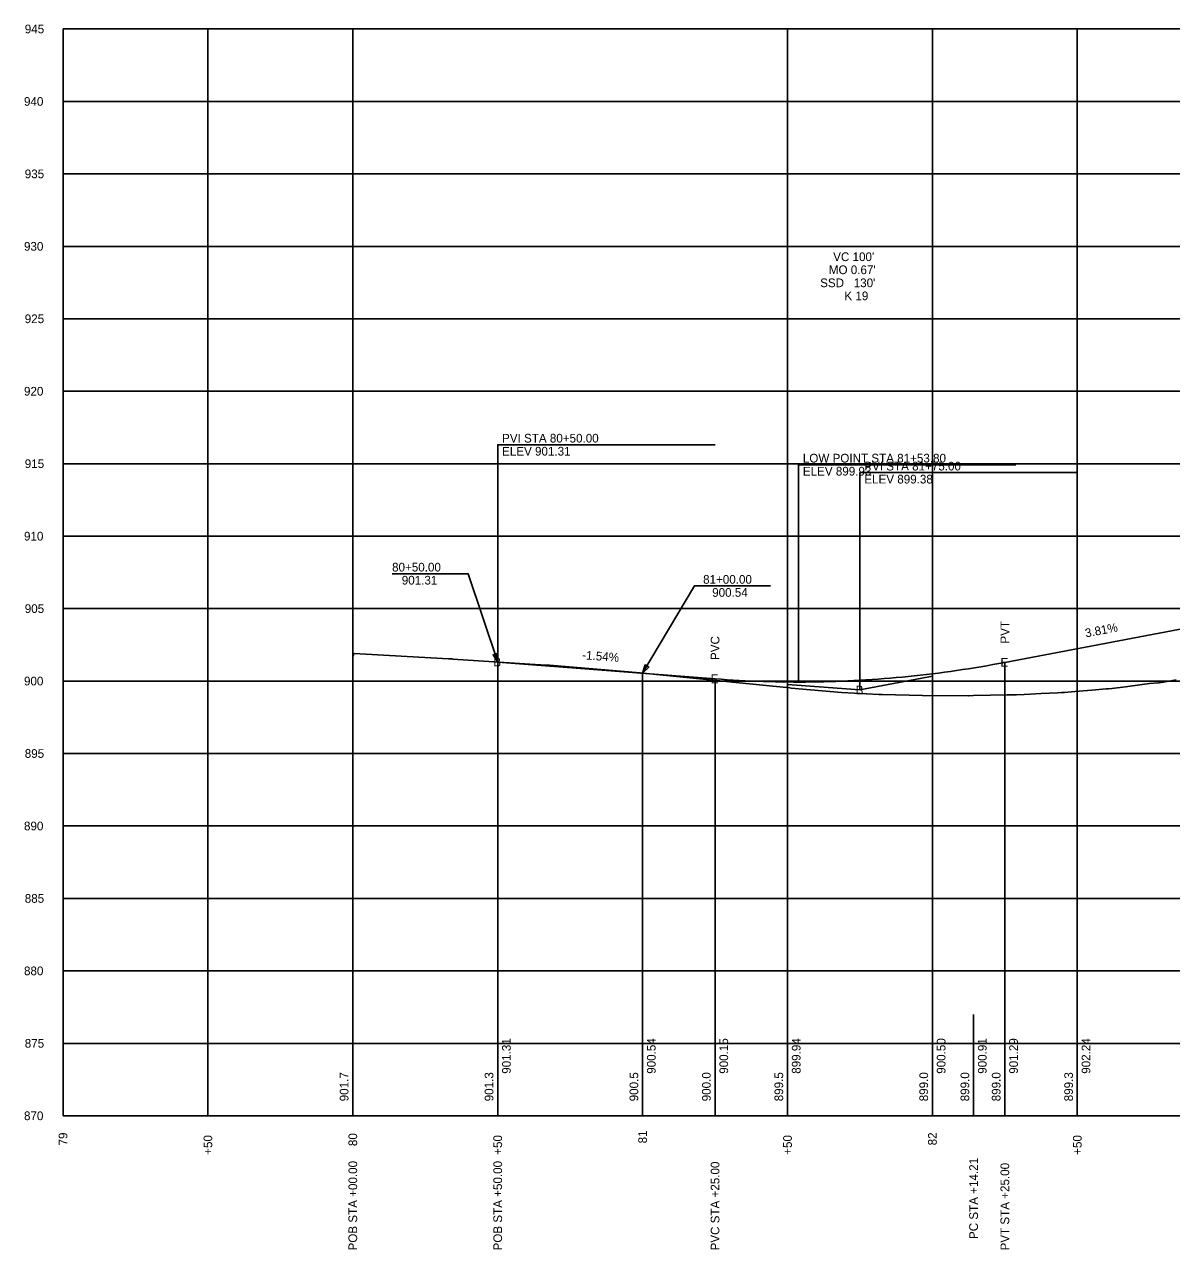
# Model space of a CAD drawing. Extents: x 76292 to 78417, y 50412 to 52585.
# Drawn here: x 76292.1 to 76687.8, y 51114.2 to 51536.9 of the extents above; entities that cross this region are included whole.
import ezdxf

# ---------------------------------------------------------------- set-up
doc = ezdxf.new("R2010")
doc.units = 0
for name, color, linetype in [('1', 7, 'Continuous'), ('2', 7, 'Continuous'), ('3', 7, 'Continuous'), ('32', 7, 'Continuous'), ('33', 7, 'Continuous'), ('63', 7, 'Continuous'), ('Default', 7, 'Continuous')]:
    doc.layers.add(name, color=color, linetype=linetype)

msp = doc.modelspace()

# ---------------------------------------------------------------- linework, layer by layer
at = {"layer": '1'}
for p, q in [((76305.34, 51160.35), (78405.34, 51160.35)), ((76305.34, 51160.35), (76305.34, 51160.35)), ((76355.34, 51160.35), (76355.34, 51160.35)), ((76405.34, 51160.35), (76405.34, 51160.35)), ((76455.34, 51160.35), (76455.34, 51160.35)), ((76505.34, 51160.35), (76505.34, 51160.35)), ((76555.34, 51160.35), (76555.34, 51160.35)), ((76605.34, 51160.35), (76605.34, 51160.35)), ((76655.34, 51160.35), (76655.34, 51160.35))]:
    msp.add_line(p, q, dxfattribs=at)
for points in [[(76455.34, 51316.9), (76455.34, 51391.9), (76530.34, 51391.9)], [(76559.14, 51310.01), (76559.14, 51385.01), (76634.14, 51385.01)], [(76580.34, 51307.27), (76580.34, 51382.27), (76655.34, 51382.27)], [(76455.34, 51316.9), (76455.34, 51160.35), (76455.34, 51160.35), (76455.34, 51160.35)], [(76630.34, 51316.79), (76630.34, 51160.35), (76630.34, 51160.35), (76630.34, 51160.35)], [(76530.34, 51311.12), (76530.34, 51160.35), (76530.34, 51160.35), (76530.34, 51160.35)], [(76305.34, 51160.35), (76305.34, 51195.35)], [(76305.34, 51160.35), (76305.34, 51195.35)], [(76305.34, 51160.35), (76305.34, 51195.35)], [(76305.34, 51160.35), (76305.34, 51195.35)], [(76355.34, 51160.35), (76355.34, 51195.35)], [(76355.34, 51160.35), (76355.34, 51195.35)], [(76355.34, 51160.35), (76355.34, 51195.35)], [(76355.34, 51160.35), (76355.34, 51195.35)], [(76405.34, 51160.35), (76405.34, 51195.35)], [(76405.34, 51160.35), (76405.34, 51195.35)], [(76405.34, 51160.35), (76405.34, 51195.35)], [(76405.34, 51160.35), (76405.34, 51195.35)], [(76455.34, 51160.35), (76455.34, 51195.35)], [(76455.34, 51160.35), (76455.34, 51195.35)], [(76455.34, 51160.35), (76455.34, 51195.35)], [(76455.34, 51160.35), (76455.34, 51195.35)], [(76505.34, 51160.35), (76505.34, 51195.35)], [(76505.34, 51160.35), (76505.34, 51195.35)], [(76505.34, 51160.35), (76505.34, 51195.35)], [(76505.34, 51160.35), (76505.34, 51195.35)], [(76530.34, 51160.35), (76530.34, 51195.35)], [(76530.34, 51160.35), (76530.34, 51195.35)], [(76530.34, 51160.35), (76530.34, 51195.35)], [(76530.34, 51160.35), (76530.34, 51195.35)], [(76555.34, 51160.35), (76555.34, 51195.35)], [(76555.34, 51160.35), (76555.34, 51195.35)], [(76555.34, 51160.35), (76555.34, 51195.35)], [(76555.34, 51160.35), (76555.34, 51195.35)], [(76605.34, 51160.35), (76605.34, 51195.35)], [(76605.34, 51160.35), (76605.34, 51195.35)], [(76605.34, 51160.35), (76605.34, 51195.35)], [(76605.34, 51160.35), (76605.34, 51195.35)], [(76619.55, 51160.35), (76619.55, 51195.35)], [(76619.55, 51160.35), (76619.55, 51195.35)], [(76619.55, 51160.35), (76619.55, 51195.35)], [(76619.55, 51160.35), (76619.55, 51195.35)], [(76630.34, 51160.35), (76630.34, 51195.35)], [(76630.34, 51160.35), (76630.34, 51195.35)], [(76630.34, 51160.35), (76630.34, 51195.35)], [(76630.34, 51160.35), (76630.34, 51195.35)], [(76655.34, 51160.35), (76655.34, 51195.35)], [(76655.34, 51160.35), (76655.34, 51195.35)], [(76655.34, 51160.35), (76655.34, 51195.35)], [(76655.34, 51160.35), (76655.34, 51195.35)]]:
    msp.add_lwpolyline(points, dxfattribs=at)
at = {"layer": '2'}
msp.add_lwpolyline([(76405.34, 51318.83), (76405.72, 51319.85), (76405.74, 51319.85), (76405.77, 51319.85), (76405.8, 51319.85), (76405.83, 51319.85), (76405.84, 51319.85), (76409.89, 51319.63), (76438.41, 51318.04), (76438.7, 51318.02), (76439, 51318.01), (76439.5, 51317.98), (76439.8, 51317.96), (76469.99, 51315.91), (76470.25, 51315.92), (76473.18, 51315.84), (76504.5, 51313.14), (76504.62, 51313.12), (76504.68, 51313.12), (76505.52, 51313.03), (76535.43, 51310.08), (76536.4, 51309.98), (76556.09, 51307.97), (76556.59, 51307.93), (76573.97, 51306.43), (76574.05, 51306.42), (76586.85, 51305.75), (76587.97, 51305.69), (76601.91, 51305.35), (76601.93, 51305.35), (76617.76, 51305.3), (76617.89, 51305.3), (76619.55, 51305.33), (76625.37, 51305.45), (76631.19, 51305.56), (76633.97, 51305.62), (76634.41, 51305.61), (76637.01, 51305.75), (76642.83, 51306.04), (76648.65, 51306.33), (76649.9, 51306.39), (76650.97, 51306.42), (76654.48, 51306.73), (76660.3, 51307.23), (76665.3, 51307.66), (76666.12, 51307.71), (76667.28, 51307.78), (76671.94, 51308.39), (76677.76, 51309.15), (76680.3, 51309.48), (76683.39, 51309.77), (76683.58, 51309.79), (76685.13, 51310), (76689.41, 51310.77)], dxfattribs=at)
at = {"layer": '32'}
for p, q in [((76630.34, 51316.79), (76700.34, 51330.12)), ((76455.34, 51316.9), (76530.34, 51311.12))]:
    msp.add_line(p, q, dxfattribs=at)
for points in [[(76530.34, 51311.12), (76532.42, 51310.97), (76534.51, 51310.83), (76536.59, 51310.69), (76538.67, 51310.57), (76540.76, 51310.47), (76542.84, 51310.37), (76544.92, 51310.28), (76547.01, 51310.21), (76549.09, 51310.15), (76551.17, 51310.1), (76553.26, 51310.06), (76555.34, 51310.03), (76557.42, 51310.02), (76559.51, 51310.01), (76561.59, 51310.02), (76563.67, 51310.04), (76565.76, 51310.07), (76567.84, 51310.12), (76569.92, 51310.17), (76572.01, 51310.24), (76574.09, 51310.31), (76576.17, 51310.4), (76578.26, 51310.5), (76582.42, 51310.74), (76584.51, 51310.87), (76586.59, 51311.02), (76588.67, 51311.18), (76590.76, 51311.35), (76592.84, 51311.53), (76594.92, 51311.73), (76597.01, 51311.93), (76599.09, 51312.15), (76601.17, 51312.38), (76603.26, 51312.62), (76605.34, 51312.87), (76607.42, 51313.13), (76609.51, 51313.41), (76611.59, 51313.69), (76613.67, 51313.99), (76615.76, 51314.3), (76617.84, 51314.62), (76619.92, 51314.95), (76622.01, 51315.3), (76624.09, 51315.65), (76626.17, 51316.02), (76628.26, 51316.4), (76630.34, 51316.79)], [(76555.34, 51309.2), (76580.34, 51307.27), (76605.34, 51312.03)]]:
    msp.add_lwpolyline(points, dxfattribs=at)
at = {"layer": '63'}
for p, q in [((76305.34, 51160.35), (76305.34, 51535.35)), ((76305.34, 51535.35), (76305.34, 51535.35)), ((76305.34, 51535.35), (76305.34, 51535.35)), ((76305.34, 51535.35), (78405.34, 51535.35)), ((76305.34, 51535.35), (78405.34, 51535.35)), ((76355.34, 51160.35), (76355.34, 51535.35)), ((76405.34, 51160.35), (76405.34, 51535.35)), ((76555.34, 51160.35), (76555.34, 51535.35)), ((76605.34, 51160.35), (76605.34, 51535.35)), ((76655.34, 51160.35), (76655.34, 51535.35)), ((76305.34, 51510.35), (76305.34, 51510.35)), ((76305.34, 51510.35), (78405.34, 51510.35)), ((76305.34, 51485.35), (76305.34, 51485.35)), ((76305.34, 51485.35), (78405.34, 51485.35)), ((76305.34, 51460.35), (76305.34, 51460.35)), ((76305.34, 51460.35), (78405.34, 51460.35)), ((76305.34, 51435.35), (76305.34, 51435.35)), ((76305.34, 51435.35), (78405.34, 51435.35)), ((76305.34, 51410.35), (76305.34, 51410.35)), ((76305.34, 51410.35), (78405.34, 51410.35)), ((76305.34, 51385.35), (76305.34, 51385.35)), ((76305.34, 51385.35), (78405.34, 51385.35)), ((76305.34, 51360.35), (76305.34, 51360.35)), ((76305.34, 51360.35), (78405.34, 51360.35)), ((76305.34, 51335.35), (76305.34, 51335.35)), ((76305.34, 51335.35), (78405.34, 51335.35)), ((76455.34, 51160.35), (76455.34, 51316.9)), ((76505.34, 51160.35), (76505.34, 51313.05)), ((76305.34, 51310.35), (76305.34, 51310.35)), ((76305.34, 51310.35), (78405.34, 51310.35)), ((76305.34, 51285.35), (76305.34, 51285.35)), ((76305.34, 51285.35), (78405.34, 51285.35)), ((76305.34, 51260.35), (76305.34, 51260.35)), ((76305.34, 51260.35), (78405.34, 51260.35)), ((76305.34, 51235.35), (76305.34, 51235.35)), ((76305.34, 51235.35), (78405.34, 51235.35)), ((76305.34, 51210.35), (76305.34, 51210.35)), ((76305.34, 51210.35), (78405.34, 51210.35)), ((76305.34, 51185.35), (76305.34, 51185.35)), ((76305.34, 51185.35), (78405.34, 51185.35)), ((76305.34, 51160.35), (76305.34, 51160.35))]:
    msp.add_line(p, q, dxfattribs=at)
at = {"layer": 'Default'}
for p, q in [((76418.89, 51347.4), (76442.2, 51347.4)), ((76526.21, 51343.18), (76549.52, 51343.18))]:
    msp.add_line(p, q, dxfattribs=at)
for points in [[(76455.34, 51316.9), (76445.2, 51347.4), (76442.2, 51347.4)], [(76505.34, 51313.05), (76523.21, 51343.18), (76526.21, 51343.18)]]:
    msp.add_lwpolyline(points, dxfattribs=at)
for points in [[(76455.34, 51316.9), (76453.73, 51319.44), (76455.11, 51319.9)], [(76505.34, 51313.05), (76506.2, 51315.93), (76507.45, 51315.18)]]:
    msp.add_lwpolyline(points, close=True, dxfattribs=at)

# ---------------------------------------------------------------- texts
at = {"layer": '1'}
for s, p in [('80+50.00', (76418.89, 51348.15)), ('81+00.00', (76526.21, 51343.93)), ('901.31', (76422.24, 51343.65)), ('900.54', (76529.35, 51339.43))]:
    msp.add_text(s, height=3, dxfattribs=at).set_placement(p)
for s, p in [('79', (76306.84, 51150.12)), ('+50', (76356.84, 51146.89)), ('80', (76406.84, 51149.89)), ('+50', (76456.84, 51146.89)), ('81', (76506.84, 51150.83)), ('+50', (76556.84, 51146.89)), ('82', (76606.84, 51150.15)), ('+50', (76656.84, 51146.89))]:
    msp.add_text(s, height=3, rotation=90, dxfattribs=at).set_placement(p)
at = {"layer": '3'}
for s, p in [('901.7', (76403.84, 51165.35)), ('901.3', (76453.84, 51165.35)), ('900.5', (76503.84, 51165.35)), ('900.0', (76528.84, 51165.35)), ('899.5', (76553.84, 51165.35)), ('899.0', (76603.84, 51165.35)), ('899.0', (76618.05, 51165.35)), ('899.0', (76628.84, 51165.35)), ('899.3', (76653.84, 51165.35))]:
    msp.add_text(s, height=3, rotation=90, dxfattribs=at).set_placement(p)
at = {"layer": '33'}
for s, p in [("VC 100'", (76571.1, 51455.26)), ("MO 0.67'", (76569.6, 51450.76)), ("SSD   130'", (76566.6, 51446.26)), ('K 19', (76574.98, 51441.76)), ('B', (76453.84, 51315.4)), ('B', (76578.84, 51305.77))]:
    msp.add_text(s, height=3, dxfattribs=at).set_placement(p)
for s, rotation, p in [('PVI STA 80+50.00', 360, (76456.84, 51392.65)), ('ELEV 901.31', 360, (76456.84, 51388.15)), ('LOW POINT STA 81+53.80', 360, (76560.64, 51385.76)), ('PVI STA 81+75.00', 360, (76581.84, 51383.02)), ('ELEV 899.93', 360, (76560.64, 51381.26)), ('ELEV 899.38', 360, (76581.84, 51378.52)), ('PVT', 90, (76631.84, 51323.29)), ('3.81%', 10.7787, (76658.32, 51325.38)), ('PVC', 90, (76531.84, 51317.62)), ('-1.54%', 355.5969, (76484.42, 51317.91)), ('E', 360, (76628.84, 51315.29)), ('E', 360, (76528.84, 51309.62)), ('901.31', 90, (76459.84, 51174.85)), ('900.54', 90, (76509.84, 51174.85)), ('900.15', 90, (76534.84, 51174.85)), ('899.94', 90, (76559.84, 51174.85)), ('900.50', 90, (76609.84, 51174.85)), ('900.91', 90, (76624.05, 51174.85)), ('901.29', 90, (76634.84, 51174.85)), ('902.24', 90, (76659.84, 51174.85)), ('POB STA +00.00', 90, (76406.84, 51113.89)), ('POB STA +50.00', 90, (76456.84, 51113.89)), ('PVC STA +25.00', 90, (76531.84, 51113.89)), ('PC STA +14.21', 90, (76621.05, 51117.83)), ('PVT STA +25.00', 90, (76631.84, 51113.89))]:
    msp.add_text(s, height=3, rotation=rotation, dxfattribs=at).set_placement(p)
at = {"layer": '63'}
for s, height, p in [('945', 3, (76292.14, 51533.85)), ('945', 3, (76292.14, 51533.85)), ('940', 3, (76291.88, 51508.85)), ('935', 3, (76292.14, 51483.85)), ('930', 3, (76291.88, 51458.85)), ('925', 3, (76292.14, 51433.85)), ('920', 3, (76291.88, 51408.85)), ('915', 3, (76292.14, 51383.85)), ('910', 3, (76291.88, 51358.85)), ('905', 3, (76292.14, 51333.85)), ('900', 3, (76291.88, 51308.85)), ('895', 3, (76292.14, 51283.85)), ('890', 3, (76291.88, 51258.85)), ('885', 3, (76292.14, 51233.85)), ('880', 3, (76291.88, 51208.85)), ('875', 3, (76292.14, 51183.85)), ('870', 3, (76291.88, 51158.85)), ('-', 0.0025, (76305.34, 51160.35))]:
    msp.add_text(s, height=height, dxfattribs=at).set_placement(p)

doc.saveas('drawing.dxf')
